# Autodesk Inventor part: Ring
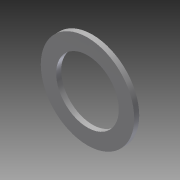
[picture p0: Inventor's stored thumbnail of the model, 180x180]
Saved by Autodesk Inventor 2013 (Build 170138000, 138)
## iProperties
Created: 2009-03
Part Number: Ring
Document SubType Name: Modeling
Designer: tangg
Density: 7.86 g/cm^3
Material: Steel, Mild
Mass: 47.3376 g
Surface Area: 38.1795 cm^2
Volume: 6.02259 cm^3
Author: tangg
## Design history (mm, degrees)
sketch "Sketch1"
  geometry: C1 r 18.78 at (-13.18, 0); C2 r 28 at (-13.18, 0) reference; C3 r 28 at (-13.18, 0) reference; C4 r 28.005 at (-13.18, 0); 1 further point
  constraints: 2 centre point, 1 coincident
  dimensions: "d3" = 0.005 radial gap between concentric circles of C2 C4
extrude "Extrusion1" new body sketch "Sketch1" distance "d0" = 3; taper "d1" = 0 deg
body "Solid1"
node "Reference2"
node "Reference3"
